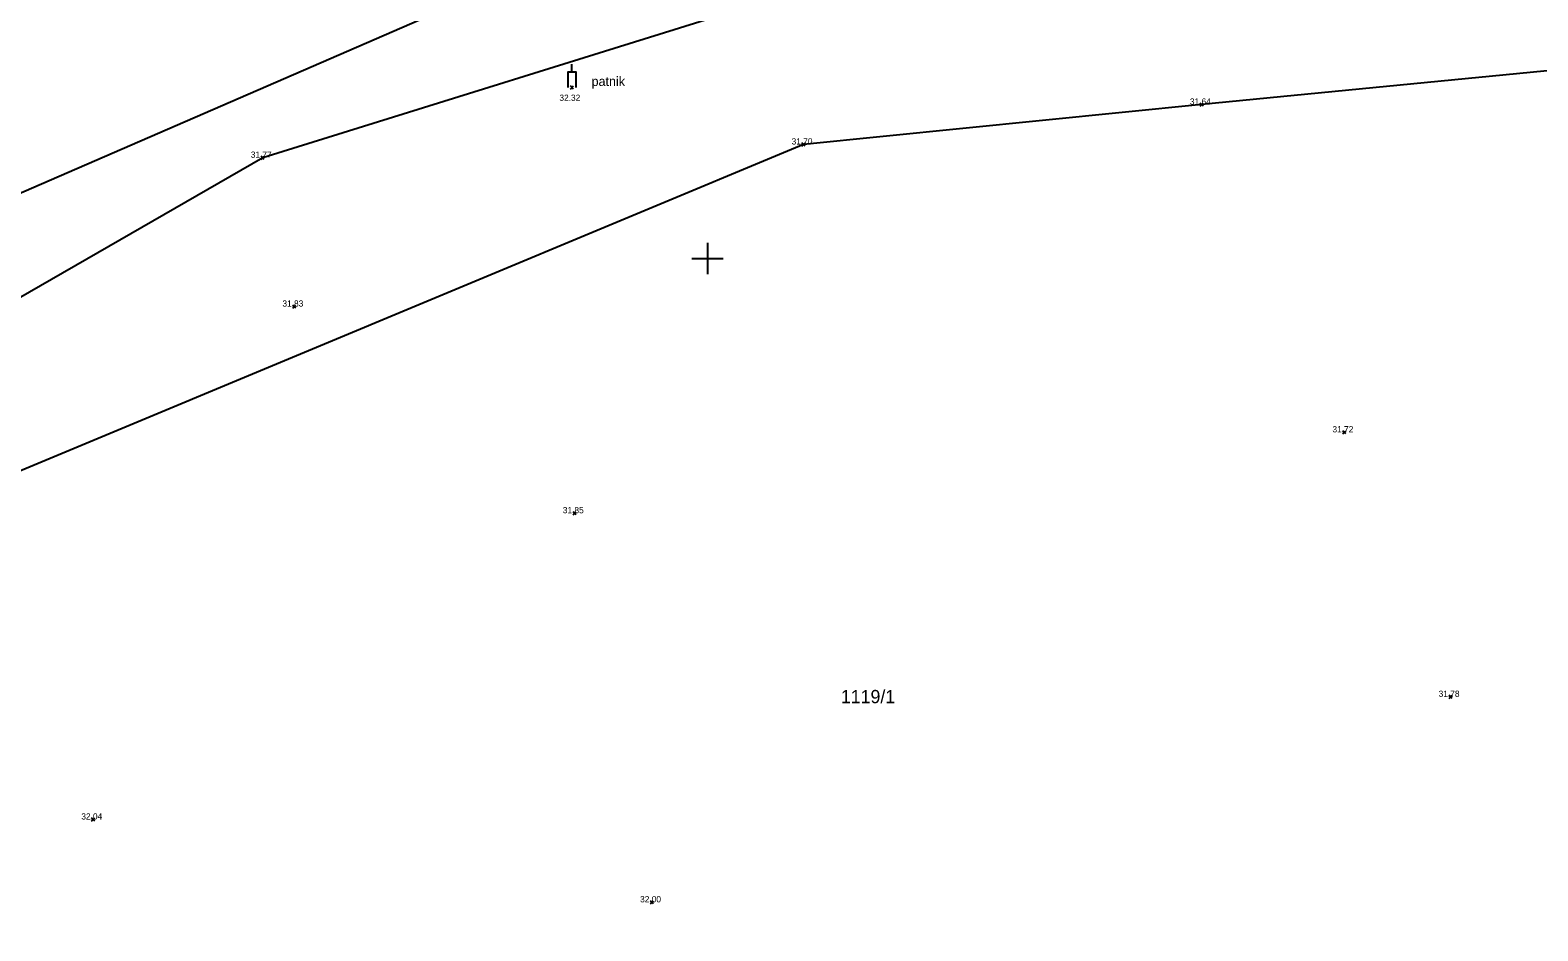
# Model space of a CAD drawing. Extents: x -772865 to -772533, y -1034366 to -1034132.
# Drawn here: x -772667.35 to -772628.73, y -1034242.21 to -1034219.15 of the extents above; entities that cross this region are included whole.
import ezdxf

# ---------------------------------------------------------------- set-up
doc = ezdxf.new("R2010")
doc.units = 0
for name, color, linetype in [('body', 7, 'Continuous'), ('KM_hranice', 7, 'Continuous'), ('KM_parcelni_cisla', 7, 'Continuous'), ('mistni_popis', 7, 'Continuous'), ('oddeleni_ploch', 7, 'Continuous'), ('ostatni_predmety', 7, 'Continuous'), ('souradnicova_sit', 7, 'Continuous'), ('stromy_kere', 7, 'Continuous'), ('vyskove_koty', 7, 'Continuous')]:
    doc.layers.add(name, color=color, linetype=linetype)

msp = doc.modelspace()

# ---------------------------------------------------------------- linework, layer by layer
at = {"layer": 'body'}
for p, q in [((-772653.43, -1034220.66), (-772653.51, -1034220.58)), ((-772653.51, -1034220.66), (-772653.43, -1034220.58)), ((-772637.3, -1034221.1), (-772637.38, -1034221.02)), ((-772637.38, -1034221.1), (-772637.3, -1034221.02)), ((-772647.5, -1034222.12), (-772647.58, -1034222.04)), ((-772647.58, -1034222.12), (-772647.5, -1034222.04)), ((-772661.35, -1034222.46), (-772661.43, -1034222.38)), ((-772661.43, -1034222.46), (-772661.35, -1034222.38)), ((-772660.54, -1034226.27), (-772660.62, -1034226.19)), ((-772660.62, -1034226.27), (-772660.54, -1034226.19)), ((-772633.65, -1034229.49), (-772633.73, -1034229.41)), ((-772633.73, -1034229.49), (-772633.65, -1034229.41)), ((-772653.36, -1034231.56), (-772653.44, -1034231.48)), ((-772653.44, -1034231.56), (-772653.36, -1034231.48)), ((-772630.93, -1034236.26), (-772631.01, -1034236.18)), ((-772631.01, -1034236.26), (-772630.93, -1034236.18)), ((-772665.69, -1034239.4), (-772665.77, -1034239.32)), ((-772665.77, -1034239.4), (-772665.69, -1034239.32)), ((-772651.38, -1034241.52), (-772651.46, -1034241.44)), ((-772651.46, -1034241.52), (-772651.38, -1034241.44))]:
    msp.add_line(p, q, dxfattribs=at)
at = {"layer": 'KM_hranice'}
msp.add_line((-772656.67, -1034218.59), (-772680.54, -1034228.95), dxfattribs=at)
at = {"layer": 'oddeleni_ploch'}
msp.add_line((-772660.58, -1034226.23), (-772660.58, -1034226.23), dxfattribs=at)
msp.add_lwpolyline([(-772569.67, -1034207.72), (-772578.35, -1034211.18), (-772588.33, -1034216.15), (-772592.11, -1034217.46), (-772598.89, -1034219.1), (-772610.21, -1034219.57), (-772621.14, -1034219.48), (-772637.34, -1034221.06), (-772647.54, -1034222.08), (-772674.34, -1034233.24), (-772685.01, -1034239.21), (-772697.33, -1034242.95), (-772712.12, -1034249.56), (-772725.85, -1034254.8), (-772738.85, -1034261.98), (-772750.37, -1034267.76), (-772764, -1034272.65), (-772783.9, -1034280.59), (-772796.38, -1034286.28), (-772810.31, -1034291.67), (-772823.61, -1034294.35), (-772828.52, -1034296.12), (-772827.01, -1034302.81), (-772823.23, -1034300.75)], dxfattribs=at)
at = {"layer": 'ostatni_predmety'}
msp.add_line((-772653.47, -1034220.22), (-772653.47, -1034220.02), dxfattribs=at)
msp.add_lwpolyline([(-772653.57, -1034220.62), (-772653.57, -1034220.22), (-772653.37, -1034220.22), (-772653.37, -1034220.62)], dxfattribs=at)
at = {"layer": 'souradnicova_sit'}
for p, q in [((-772650, -1034224.6), (-772650, -1034225.4)), ((-772650.4, -1034225), (-772649.6, -1034225))]:
    msp.add_line(p, q, dxfattribs=at)
at = {"layer": 'stromy_kere'}
msp.add_lwpolyline([(-772583.42, -1034211.72), (-772590.3, -1034214.78), (-772599.43, -1034217.31), (-772610.6, -1034216.68), (-772621.69, -1034215.38), (-772638.07, -1034215.85), (-772648.66, -1034218.46), (-772661.39, -1034222.42), (-772671.31, -1034228.13), (-772675.64, -1034228.98), (-772682.86, -1034232.81), (-772685.07, -1034236.11), (-772686.87, -1034236.8), (-772697.8, -1034241.28), (-772703.73, -1034242.07)], dxfattribs=at)

# ---------------------------------------------------------------- texts
at = {"layer": 'KM_parcelni_cisla'}
msp.add_text('1119/1', height=0.34, dxfattribs=at).set_placement((-772646.583, -1034236.383))
at = {"layer": 'mistni_popis'}
msp.add_text('patnik', height=0.24, dxfattribs=at).set_placement((-772652.968, -1034220.582))
at = {"layer": 'vyskove_koty'}
for s, p in [('32.32', (-772653.792, -1034220.962)), ('31.64', (-772637.645, -1034221.06)), ('31.70', (-772647.845, -1034222.08)), ('31.77', (-772661.695, -1034222.42)), ('31.83', (-772660.885, -1034226.23)), ('31.72', (-772633.995, -1034229.45)), ('31.85', (-772653.705, -1034231.52)), ('31.78', (-772631.275, -1034236.22)), ('32.04', (-772666.035, -1034239.36)), ('32.00', (-772651.725, -1034241.48))]:
    msp.add_text(s, height=0.16, dxfattribs=at).set_placement(p)

doc.saveas('drawing.dxf')
